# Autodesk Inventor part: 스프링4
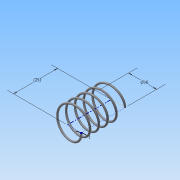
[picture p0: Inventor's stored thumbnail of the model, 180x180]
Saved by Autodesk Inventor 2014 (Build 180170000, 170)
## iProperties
Created: 2015-06
Part Number: 스프링4
Material: 강철, 연강
Document SubType Name: Modeling
Designer: Administrator
Density: 7.86 g/cm^3
Appearance: 강철
Mass: 1.52988 g
Surface Area: 7.87024 cm^2
Volume: 0.194641 cm^3
Author: Administrator
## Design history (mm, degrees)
sketch "스케치1"
  geometry: L1 (0, 0)-(8, 0); L2 (8, 0)-(8, 14.5); L3 (8, 14.5)-(0, 14.5); L4 (0, 14.5)-(0, 0); C1 r 0.5 at (8, 0)
  constraints: 8 end point, 2 parallel, 1 centre point, 1 coincident, 1 horizontal, 1 perpendicular
  dimensions: "d0" = 14.5 distance of L3.end L1.start (derived); "d1" = 16 diameter of L2 L4; "d2" = 1 diameter of C1
feature "코일1" sketch "스케치1" pitch "d3" = 10; turns "d5" = 5; dims "d4" = 14.5 (= d0), "d6" = 0, angle "d7" = 90 deg, angle "d8" = 90 deg, "d9" = 0, "d10" = 0
sketch "스케치2"
  geometry: L1 (-8.5, 0)-(-7.5, 0) reference; 1 further point
  constraints: 1 horizontal alignment
extrude "돌출1" cut sketch "스케치2" distance "d11" = 10; taper "d12" = 0 deg
node "작업 평면1"
sketch "스케치3"
  geometry: L1 (-7.5, 0)-(-8.5, 0) reference; 1 further point
  constraints: 1 horizontal alignment
extrude "돌출2" cut sketch "스케치3" distance "d14" = 10; taper "d15" = 0 deg
node "솔리드1"
node "절단 모서리 투영1"
node "절단 모서리 투영2"
other parameters: "d13" = 14.5 (= d0)
